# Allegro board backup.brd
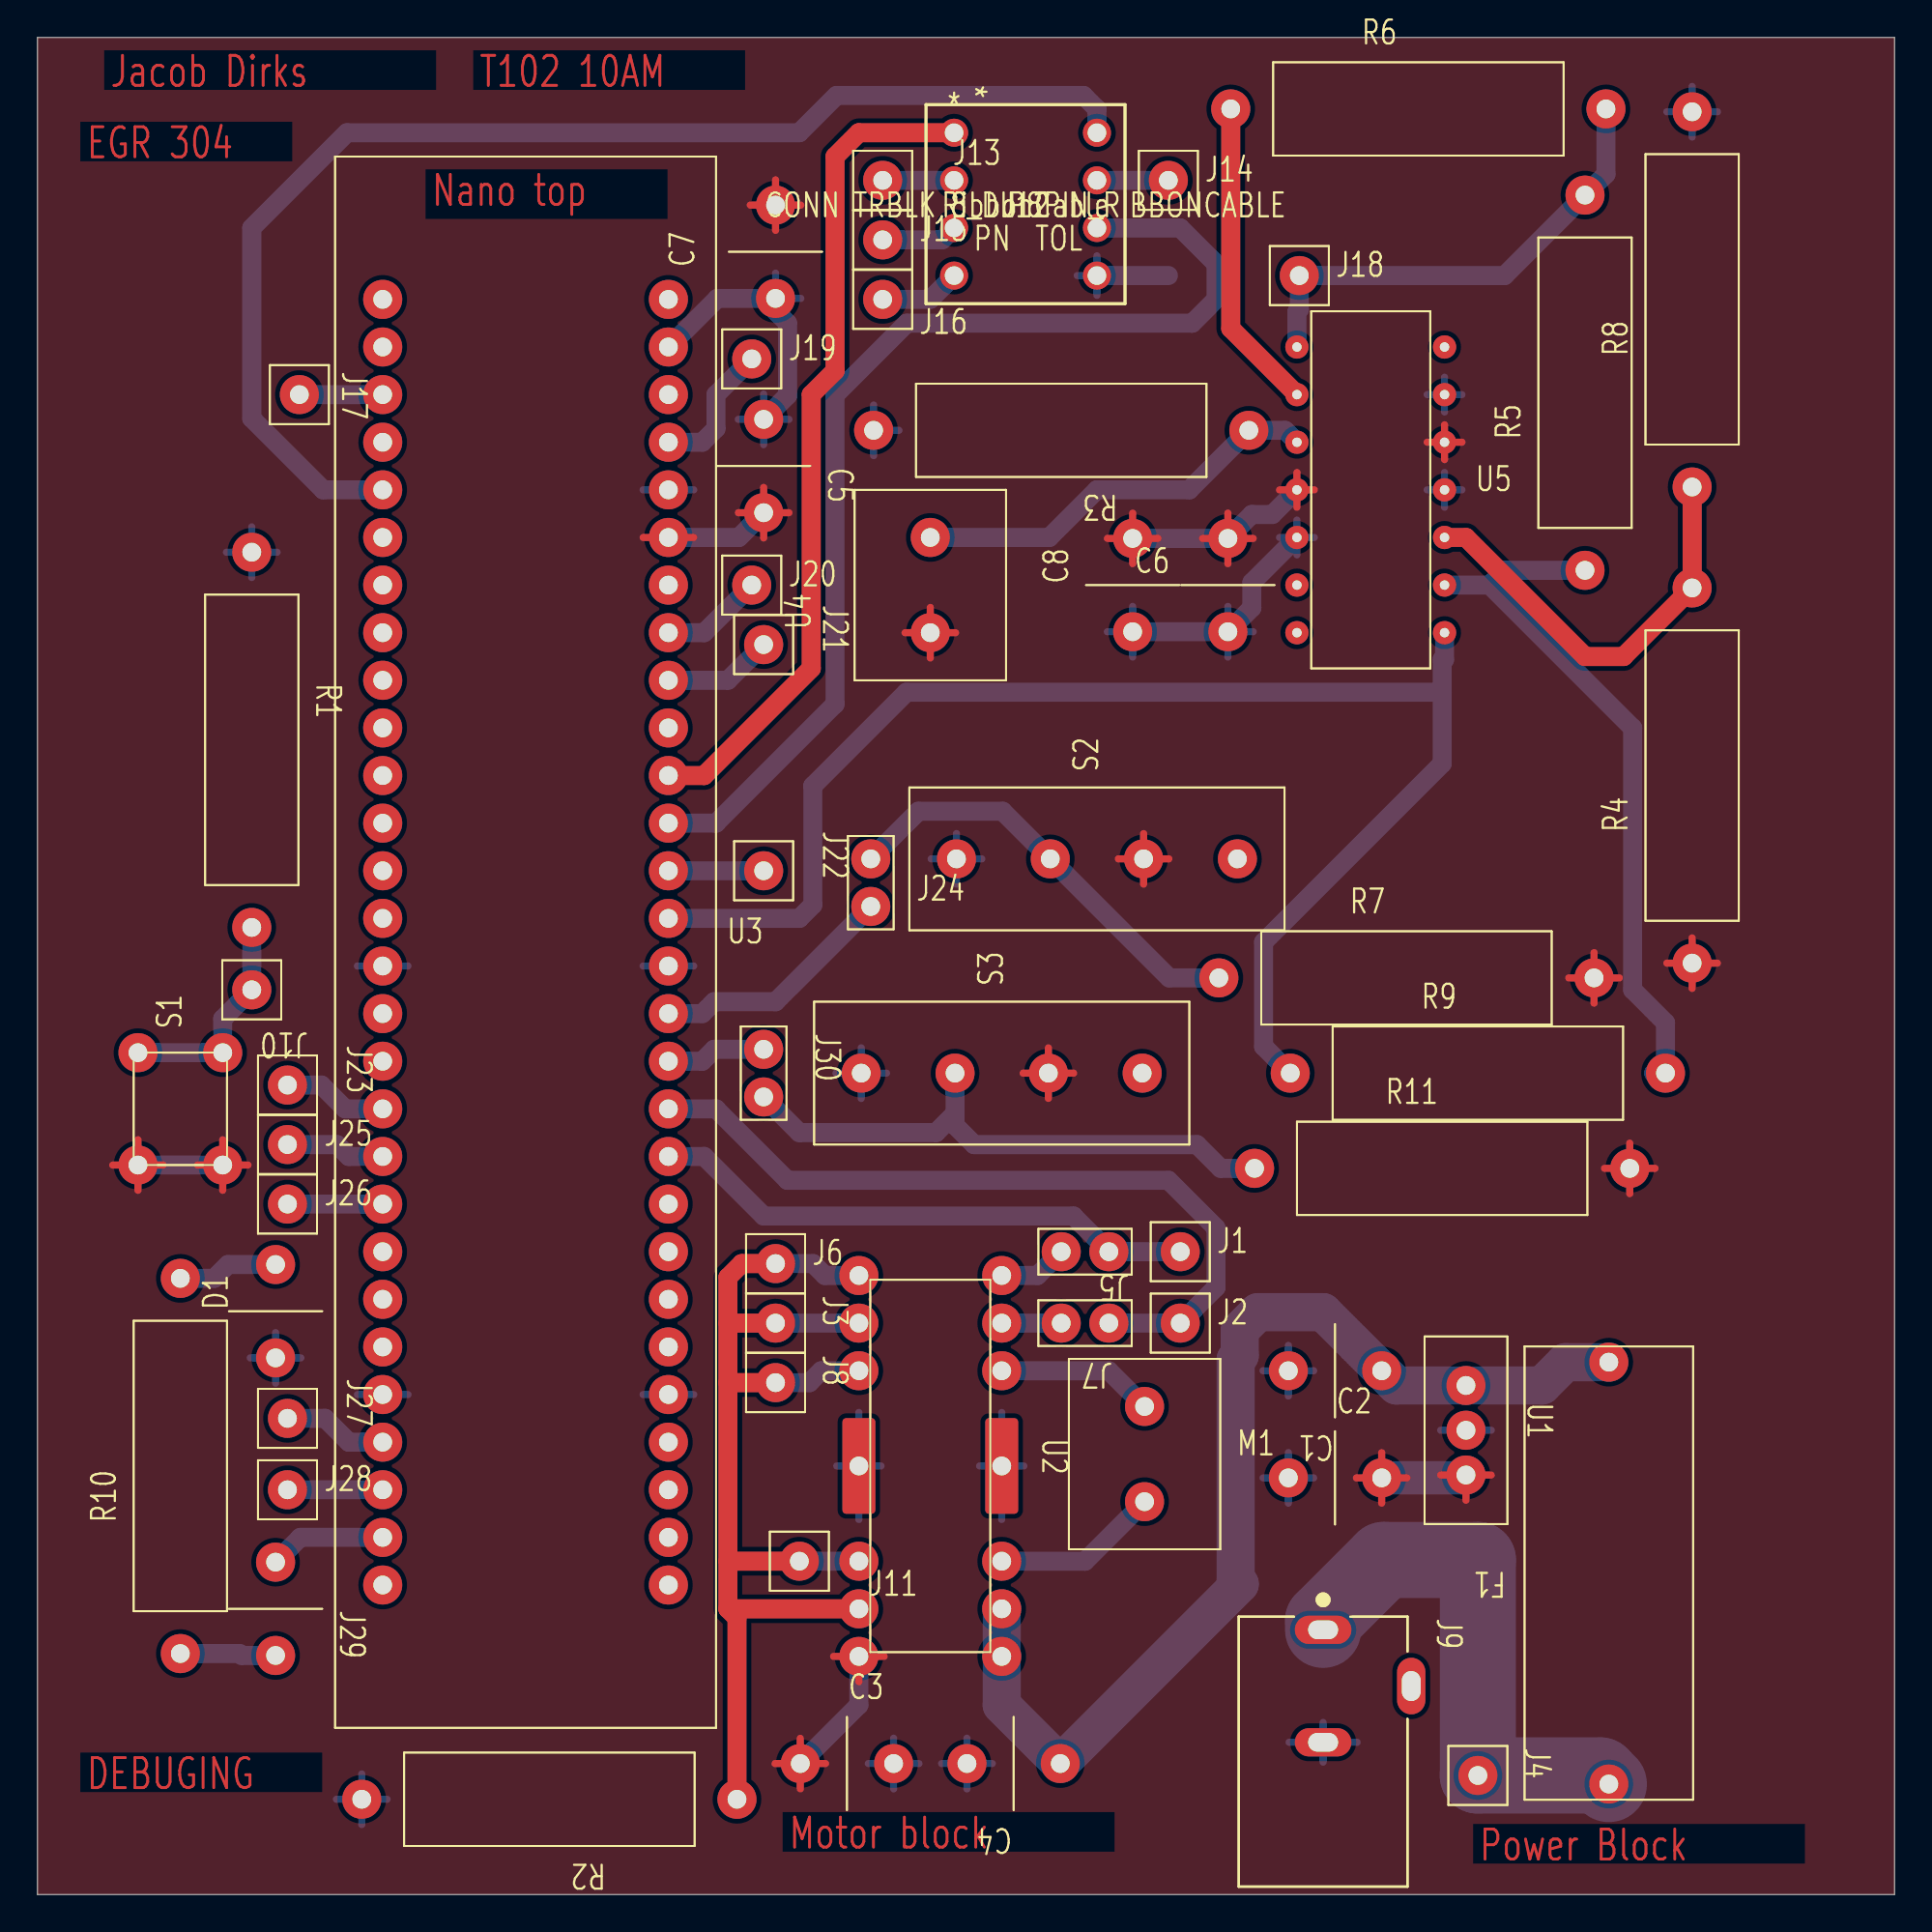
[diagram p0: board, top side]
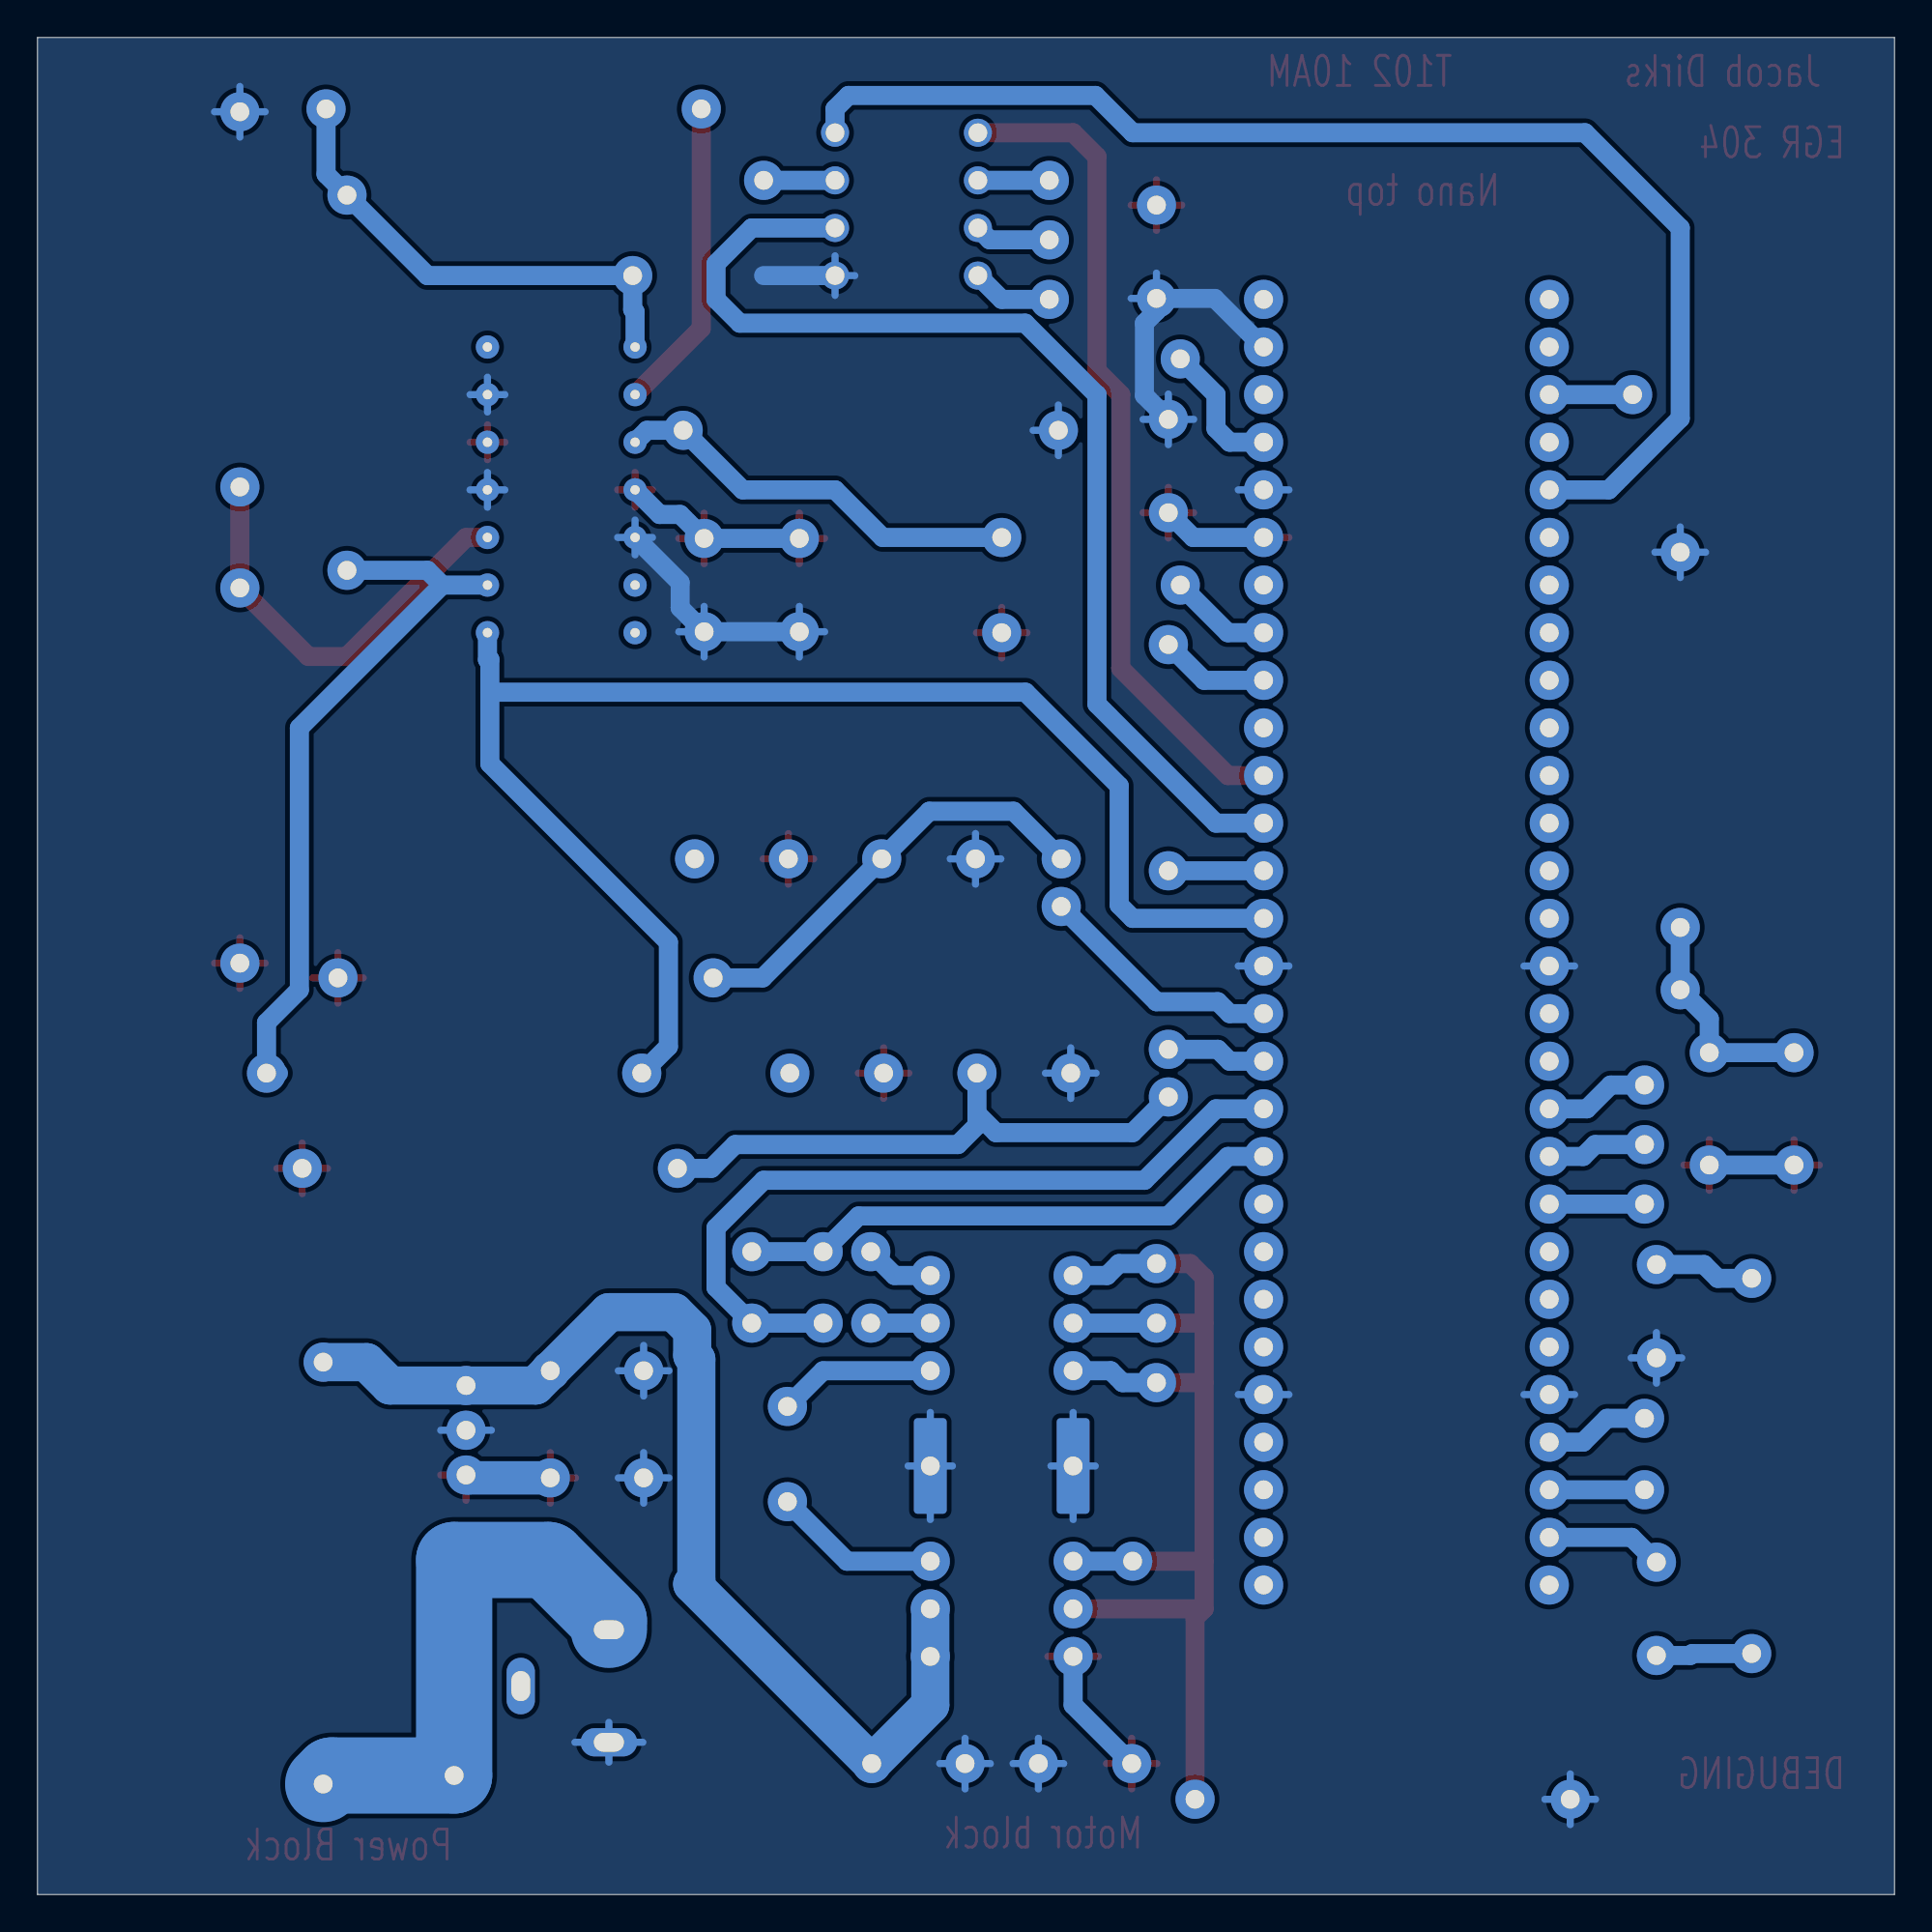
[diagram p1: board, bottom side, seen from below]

Outline 99.06 x 99.06 mm; copper layers: TOP, BOTTOM. Coordinates in mm from the lower left corner of the outline.
Outline path: 0,99.06 0,0 99.06,0 99.06,99.06 0,99.06

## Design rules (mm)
constraint set DEFAULT: min track width 0.381
net group N934900: nets N93718 N934900

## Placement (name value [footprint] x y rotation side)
C1  .33uf 50V  [CAPACITOR]  69.22 27.94 180 top
C2  .1uF 50V  [CAPACITOR]  69.22 22.22 0 top
C3  .1uF 50V  [CAPACITOR]  43.18 6.99 0 top
C4  .1uF 50V  [CAPACITOR]  52.07 6.99 180 top
C5  .1uF 50V  [CAPACITOR]  38.73 76.2 270 top
C6  .1uF 50V  [CAPACITOR]  63.5 69.85 90 top
C7  .1uF 50V  [CAPACITOR]  39.37 87.63 90 top
C8  .1uF 50V  [CAPACITOR]  58.42 69.85 90 top
D1  BlueLED  [CAPACITOR]  12.7 31.12 90 top
F1  FUSE 1A  [FUSEHOLDER]  83.82 17.15 180 top
J1  TP2  [MALEPINHOLE]  60.96 34.29 0 top
J2  TP3  [MALEPINHOLE]  60.96 30.48 0 top
J3  TP5  [MALEPINHOLE]  39.37 30.48 0 top
J4  TP12  [MALEPINHOLE]  76.83 6.35 0 top
J5  Jumper_JMD  [JUMPER]  55.88 34.29 270 top
J6  TP4  [MALEPINHOLE]  39.37 33.66 0 top
J7  Jumper_JMD  [JUMPER]  55.88 30.48 270 top
J8  TP6  [MALEPINHOLE]  39.37 27.31 0 top
J9  Barrel_Jack_Switch_JMD  [BARRELJACKDEVELOPERS_JMD]  68.58 7.62 270 top
J10  TP13  [MALEPINHOLE]  11.43 48.26 270 top
J11  TP7  [MALEPINHOLE]  40.64 17.78 0 top
J12  RibbonCable  [DIP8PIN]  48.89 93.98 0 top
J13  TP8  [MALEPINHOLE]  45.09 91.44 0 top
J14  TP9  [MALEPINHOLE]  60.33 91.44 0 top
J15  TP10  [MALEPINHOLE]  45.09 88.26 0 top
J16  TP11  [MALEPINHOLE]  45.09 85.09 0 top
J17  gpio_RF0  [MALEPINHOLE]  13.97 80.01 0 top
J18  TP1  [MALEPINHOLE]  67.31 86.36 0 top
J19  gpio_RB7  [MALEPINHOLE]  38.1 81.92 0 top
J20  gpio_RA6  [MALEPINHOLE]  38.1 69.85 0 top
J21  gpio_RB3  [MALEPINHOLE]  38.73 66.68 0 top
J22  gpio_RA1  [MALEPINHOLE]  38.73 54.61 0 top
J23  gpio_RE2  [MALEPINHOLE]  13.34 43.18 0 top
J24  Jumper_JMD  [JUMPER]  44.45 53.97 0 top
J25  gpio_RC7  [MALEPINHOLE]  13.34 40 0 top
J26  gpio_RD0  [MALEPINHOLE]  13.34 36.83 0 top
J27  gpio_RF0  [MALEPINHOLE]  13.34 25.4 0 top
J28  gpio_RF1  [MALEPINHOLE]  13.34 21.59 0 top
J29  Jumper_JMD  [CAPACITOR]  12.7 15.24 270 top
J30  Jumper_JMD  [JUMPER]  38.73 43.81 0 top
M1  Motor_DC_JMD  [SCREWTERMINAL]  59.06 23.5 0 top
R1  1k .25w  [RESISTOR_INTRO]  11.43 61.59 270 top
R2  1k .25w  [RESISTOR_INTRO]  27.31 5.08 180 top
R3  10k .25W  [RESISTOR_INTRO]  54.61 78.11 180 top
R4  10k .25W  [RESISTOR_INTRO]  88.27 59.69 90 top
R5  1k .25w  [RESISTOR_INTRO]  82.55 80.64 90 top
R6  1k .25w  [RESISTOR_INTRO]  73.66 95.25 0 top
R7  10k .25W  [RESISTOR_INTRO]  73.03 48.9 0 top
R8  10k .25W  [RESISTOR_INTRO]  88.27 85.09 90 top
R9  10k .25W  [RESISTOR_INTRO]  76.83 43.81 0 top
R10  220 .25W  [RESISTOR_INTRO]  7.62 22.86 90 top
R11  10k .25W  [RESISTOR_INTRO]  74.93 38.74 0 top
S1  SW_DPST_JMD  [SW_DPST]  7.62 41.91 90 top
S2  Switch_limit_JMD  [LIMITSWITCH]  56.52 55.25 90 top
S3  Switch_limit_JMD  [LIMITSWITCH]  51.44 43.81 90 top
U1  LM7805_JMD  [LINEARVOLTREG]  76.2 24.77 0 top
U2  FAN8011N_JMD  [HBRIDGEWITHFIN]  45.09 22.86 0 top
U3  PIC18F57Q43_JMD  [MICROCHIP_PIC18F57Q43]  26.03 50.8 0 top
U4  MS_JMD  [SCREWTERMINAL]  47.62 69.85 180 top
U5  MCP6004_JMD  [OPAMPJMD]  71.12 74.93 0 top

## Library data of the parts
C1-C8 = CAPACITOR NON-POL
D1 = LED
F1 = FUSE
J1-J4 J6 J10 J13-J17 J20-J23 J25-J28 = MalePinPlaceHolder_JMD
J5 J7 J24 J29 J30 = jumper_jmd
J8 = malePinPlaceHolderOutput_JMD_0
J9 = Barrel_Jack_Switch_JMD
J11 = malePinPlaceHolderOutput_JMD_1
J12 = CONN TRBLK 8: User Part Number: PN; Tolerance: TOL
J18 = MalePinPlaceHolder_JMD_6
J19 = malePinPlaceHolderOutput_JMD
M1 = Motor_DC_JMD
R1-R11 = RESISTOR
S1 = SW_DPST_JMD
S2 S3 = 463093691402_Limit_JMD
U1 = LM7805_JMD_0
U2 = FAN8011N_JMD_2
U3 = PIC18F57Q43_JMD
U4 = MoistureSenosr_JMD
U5 = MCP6004_JMD

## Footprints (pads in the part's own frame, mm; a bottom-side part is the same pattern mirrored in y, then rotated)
BARRELJACKDEVELOPERS_JMD
  oval 1.508x3.016 hole 1x1.6: 1(-6.5,0) 2(-0.5,0)
  oval 3.016x1.508 hole 1.6x1: 3(-3.5,4.7)
CAPACITOR
  round 2.083 hole 1.001: 1(-2.489,0) 2(2.489,0)
DIP8PIN
  round 1.499 hole 0.991: 1(0,0) 2(7.62,0) 3(0,-2.54) 4(7.62,-2.54) 5(0,-5.08) 6(7.62,-5.08) 7(0,-7.62) 8(7.62,-7.62)
FUSEHOLDER
  round 2.083 hole 1.001: 1(0,11.252) 2(0,-11.252)
HBRIDGEWITHFIN
  round 2.083 hole 1.001: 1(-1.27,10.16) 2(-1.27,7.62) 3(-1.27,5.08) 4(-1.27,-5.08) 5(-1.27,-7.62) 6(-1.27,-10.16) 7(6.35,-10.16) 8(6.35,-7.62) 9(6.35,-5.08) 10(6.35,5.08) 11(6.35,7.62) 12(6.35,10.16)
  rrect 1.753x5.1 hole 1.001: FIN(-1.27,0) FIN2(6.35,0)
JUMPER
  round 2.083 hole 1.001: 1(0,1.27) 2(0,-1.27)
LIMITSWITCH
  round 2.083 hole 1.001: 1(0,7.493) 2(0,2.489) 3(0,-2.489) 4(0,-7.493)
LINEARVOLTREG
  round 2.083 hole 1.001: 1(0,2.388) 2(0,0) 3(0,-2.388)
MALEPINHOLE
  round 2.083 hole 1.001: 1(0,0)
MICROCHIP_PIC18F57Q43
  round 2.083 hole 1.001: 1(7.62,34.29) 2(7.62,31.75) 3(7.62,29.21) 4(7.62,26.67) 5(7.62,24.13) 6(7.62,21.59) 7(7.62,19.05) 8(7.62,16.51) 9(7.62,13.97) 10(7.62,11.43) 11(7.62,8.89) 12(7.62,6.35) 13(7.62,3.81) 14(7.62,1.27) 15(7.62,-1.27) 16(7.62,-3.81) 17(7.62,-6.35) 18(7.62,-8.89) 19(7.62,-11.43) 20(7.62,-13.97) 21(7.62,-16.51) 22(7.62,-19.05) 23(7.62,-21.59) 24(7.62,-24.13) 25(7.62,-26.67) 26(7.62,-29.21) 27(7.62,-31.75) 28(7.62,-34.29) 29(-7.62,34.29) 30(-7.62,31.75) 31(-7.62,29.21) 32(-7.62,26.67) 33(-7.62,24.13) 34(-7.62,21.59) 35(-7.62,19.05) 36(-7.62,16.51) 37(-7.62,13.97) 38(-7.62,11.43) 39(-7.62,8.89) 40(-7.62,6.35) 41(-7.62,3.81) 42(-7.62,1.27) 43(-7.62,-1.27) 44(-7.62,-3.81) 45(-7.62,-6.35) 46(-7.62,-8.89) 47(-7.62,-11.43) 48(-7.62,-13.97) 49(-7.62,-16.51) 50(-7.62,-19.05) 51(-7.62,-21.59) 52(-7.62,-24.13) 53(-7.62,-26.67) 54(-7.62,-29.21) 55(-7.62,-31.75) 56(-7.62,-34.29)
OPAMPJMD
  round 1.245 hole 0.5: 1(-3.937,7.62) 2(-3.937,5.08) 3(-3.937,2.54) 4(-3.937,0) 5(-3.937,-2.54) 6(-3.937,-5.08) 7(-3.937,-7.62) 8(3.937,-7.62) 9(3.937,-5.08) 10(3.937,-2.54) 11(3.937,0) 12(3.937,2.54) 13(3.937,5.08) 14(3.937,7.62)
RESISTOR_INTRO
  round 2.083 hole 1.001: 1(-10.008,0) 2(10.008,0)
SCREWTERMINAL
  round 2.083 hole 1.001: 1(0,2.54) 2(0,-2.54)
SW_DPST
  round 2.083 hole 1.001: 1(-2.997,2.261) 2(2.997,2.261) 3(-2.997,-2.261) 4(2.997,-2.261)

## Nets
+5V: C2.2 C3.1 C5.2 C6.2 C7.2 C8.2 R4.1 R7.2 R11.2 S1.1(\PASSIVE\) S1.3 S2.3 S3.3 U1.3(\OUTPUT\) U2.6(\VCC\) U3.6(\VTG\) U4.1 U5.4 U5.12
+9V: C1.1 C4.1 F1.2 U1.1 U2.7 U2.8
GND: C1.2 C2.1 C3.2 C4.2 C5.1 C6.1 C7.1 C8.1 D1.1(\CATHODE\) J9.2(\SPRING\) J12.8 R1.1 R2.2 R3.2 R8.2 S2.1 S3.1 U1.2 U2.FIN U2.FIN2 U3.2 U3.5 U3.15 U3.24 U3.43 U3.52 U5.5 U5.11(\VSS\) U5.13
VBUS: U3.1
AMPSIG: R5.1 R9.2 U5.9
BACKLIMIT: J30.1 U3.17
INVAMP: R6.1 U5.2
MRETURN: J12.6 U3.12
MSOUT: R9.1 U3.14 U5.8
OUT1: J18.1(\PORT\) R5.2 R6.2 U5.1
PSIGNAL: J12.1 U3.11
RSIGNAL: J12.2 U3.33
SIGBACK: J1.1(\PORT\) J5.1 U3.19
SIGFORWARD: J2.1(\PORT\) J7.1 U3.18
VREF: R4.2 R8.1 U5.10
N91840: J3.1(\PORT\) J6.1(\PORT\) J8.1 J11.1 R2.1 U2.1 U2.2 U2.3 U2.4 U2.5
N91848: J7.2 U2.11
N91894: M1.1 U2.10
N91902: F1.1 J4.1(\PORT\) J9.1
N92202: M1.2(-) U2.9
N93412: J24.2 U3.16
N93642: J27.1(\PORT\) U3.53
N93710: J29.1 U3.55
N93718: J29.2 R10.1
N93780: J30.2 R11.1 S3.2
N113659: J10.1(\PORT\) R1.2 S1.2 S1.4
N116351: J24.1 R7.1 S2.2
N125765: R3.1 U4.2 U5.3
N129031: J12.4 J14.1(\PORT\)
N923142: J12.3 J13.1(\PORT\)
N923144: J12.5 J15.1(\PORT\)
N923146: J12.7 J16.1(\PORT\)
N926043: J19.1 U3.4
N926047: J20.1(\PORT\) U3.8
N926048: J21.1(\PORT\) U3.9
N934900: D1.2 R10.2
N9170211: J5.2 U2.12
N9260427: J17.1(\PORT\) U3.31
N9260442: J23.1(\PORT\) U3.46
N9260443: J25.1(\PORT\) U3.47
N9260444: J26.1(\PORT\) U3.48
N9260450: J28.1(\PORT\) U3.54
N9260454: J22.1(\PORT\) U3.13

Pads without a net: J9 3; S2 4; S3 4; U3 3 7 10 20 21 22 23 25 26 27 28 29 30 32 34 35 36 37 38 39 40 41 42 44 45 49 50 51 56; U5 6 7 14

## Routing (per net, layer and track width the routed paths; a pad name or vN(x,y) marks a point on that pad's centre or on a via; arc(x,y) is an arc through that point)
+5V: length 125.2
  TOP w0.381: U5.12 75.06,78.4 ; U5.12 75.06,76.54 ; U5.12 74.13,77.47 ; U5.12 75.98,77.47 ; C6.2 64.85,72.34 ; C6.2 62.15,72.34 ; C6.2 63.5,73.69 ; C6.2 63.5,70.99 ; 47.62,65.96 U4.1 ; U4.1 46.28,67.31 ; U4.1 47.62,68.66 ; U4.1 48.97,67.31 ; S3.3 53.92,45.16 ; S3.3 53.92,42.47 ; S3.3 52.58,43.81 ; S3.3 55.27,43.81 ; S1.1 6.71,38.91 ; S1.1 5.36,37.57 ; S1.1 4.01,38.91 ; S1.1 5.36,40.26 ; 58.42,70.99 C8.2 ; C8.2 58.42,73.69 ; C8.2 59.77,72.34 ; C8.2 57.07,72.34 ; R7.2 84.38,48.9 ; R7.2 83.03,47.55 ; R7.2 81.69,48.9 ; R7.2 83.03,50.24 ; 71.7,20.88 C2.2 ; C2.2 71.7,23.57 ; C2.2 70.36,22.22 ; C2.2 73.05,22.22 ; C3.1 42.04,6.99 ; C3.1 40.69,5.64 ; C3.1 39.34,6.99 ; C3.1 40.69,8.33 ; R4.1 88.27,51.03 ; R4.1 89.61,49.68 ; R4.1 88.27,48.34 ; R4.1 86.92,49.68 ; 43.81,11.35 U2.6 ; U2.6 45.16,12.7 ; U2.6 42.47,12.7 ; U5.4 68.11,74.93 ; U5.4 66.26,74.93 ; U5.4 67.18,75.86 ; U5.4 67.18,74 ; S2.3 59,56.59 ; S2.3 59,53.9 ; S2.3 60.35,55.25 ; S2.3 57.66,55.25 ; 74.85,22.38 U1.3 ; U1.3 77.55,22.38 ; U1.3 76.2,21.03 ; R11.2 84.94,40.08 ; R11.2 86.28,38.74 ; R11.2 83.59,38.74 ; R11.2 84.94,37.39 ; 38.02,90.12 C7.2 ; C7.2 39.37,88.77 ; C7.2 39.37,91.47 ; C7.2 40.72,90.12 ; C5.2 40.08,73.71 ; C5.2 37.39,73.71 ; C5.2 38.73,72.36 ; C5.2 38.73,75.06 ; 8.53,38.91 S1.3 ; S1.3 9.88,40.26 ; S1.3 9.88,37.57 ; S1.3 11.23,38.91 ; 35,72.39 U3.6 32.31,72.39
  BOTTOM w1.016: S1.1 S1.3 ; U3.6 37.41,72.39 C5.2 ; U2.6 43.81,10.11 C3.1 ; C8.2 C6.2 64.78,73.62 65.87,73.62 U5.4
  BOTTOM w1.778: C2.2 76.05,22.22 U1.3
+9V: length 59
  BOTTOM w2.032: F1.2 81.5,28.4 80.26,27.15 U1.1 72.49,27.15 C1.1 68.58,31.06 65.1,31.06 64.14,30.1 64.14,28.77 63.91,28.55 63.91,16.78 64.14,16.56 C4.1 51.44,10.11 U2.7 U2.8
GND: length 156.2
  BOTTOM w0.381: S3.1 45.29,43.81 ; S3.1 43.94,45.17 ; S3.1 43.94,42.46 ; S3.1 42.59,43.81 ; J9.2 70.39,8.12 ; J9.2 68.58,9.18 ; J9.2 66.77,8.12 ; J9.2 68.58,7.06 ; R2.2 17.3,6.43 ; R2.2 15.95,5.08 ; R2.2 17.3,3.73 ; R2.2 18.65,5.08 ; C4.2 49.58,8.34 ; C4.2 50.93,6.99 ; C4.2 48.23,6.99 ; C4.2 49.58,5.63 ; 40.72,85.14 C7.1 39.37,86.49 ; R3.2 45.95,78.11 ; R3.2 44.6,76.75 ; R3.2 44.6,79.46 ; 45.67,5.63 C3.2 ; C3.2 44.32,6.99 ; C3.2 45.67,8.34 ; C3.2 47.02,6.99 ; 74.85,24.77 U1.2 77.55,24.77 ; 43.81,20 U2.FIN ; U2.FIN 43.81,25.72 ; U2.FIN 45,22.86 ; U2.FIN 42.63,22.86 ; 65.38,27.94 C1.2 ; C1.2 66.73,26.59 ; C1.2 66.73,29.29 ; C1.2 68.08,27.94 ; U5.11 75.06,75.86 ; U5.11 75.98,74.93 ; U5.11 74.13,74.93 ; U5.11 75.06,74 ; U5.5 67.18,73.32 ; U5.5 68.11,72.39 ; U5.5 66.26,72.39 ; U5.5 67.18,71.46 ; R8.2 89.62,95.1 ; R8.2 86.91,95.1 ; R8.2 88.27,96.45 ; R8.2 88.27,93.75 ; 35.01,74.93 U3.5 32.3,74.93 ; 17.06,26.67 U3.52 19.77,26.67 ; 57.07,67.36 C8.1 ; C8.1 58.42,68.71 ; C8.1 58.42,66.01 ; U5.13 75.06,80.94 ; U5.13 75.06,79.08 ; U5.13 75.98,80.01 ; U5.13 74.13,80.01 ; 38.73,77.34 C5.1 ; C5.1 38.73,80.04 ; C5.1 37.38,78.69 ; C5.1 40.09,78.69 ; 32.3,49.53 U3.15 35.01,49.53 ; C2.1 66.73,23.58 ; C2.1 65.38,22.22 ; C2.1 66.73,20.87 ; C2.1 68.08,22.22 ; 10.08,71.6 R1.1 ; R1.1 11.43,70.25 ; R1.1 12.78,71.6 ; R1.1 11.43,72.95 ; D1.1 12.7,29.98 ; D1.1 14.05,28.63 ; D1.1 12.7,27.28 ; D1.1 11.35,28.63 ; C6.1 63.5,68.71 ; C6.1 64.85,67.36 ; C6.1 63.5,66.01 ; 35.01,26.67 U3.24 32.3,26.67 ; 49.02,53.89 S2.1 ; S2.1 49.02,56.6 ; S2.1 50.37,55.25 ; S2.1 47.67,55.25 ; U2.FIN2 52.62,22.86 ; U2.FIN2 50.25,22.86 ; U2.FIN2 51.44,20 ; U2.FIN2 51.44,25.72 ; 19.77,49.53 U3.43 17.06,49.53 ; 55.46,86.36 J12.8 ; J12.8 56.52,85.31 ; J12.8 56.52,87.41
  BOTTOM w1.016: 60.33,86.36 J12.8 ; U3.2 33.67,82.55 36.26,85.14 C7.1 39.37,84.46 40.01,83.82 40.01,79.97 C5.1 ; U5.5 64.78,69.99 64.78,68.64 C6.1 C8.1
AMPSIG: length 38.4
  BOTTOM w1.016: 86.21,43.81 R9.2 86.84,46.51 85.09,48.26 85.09,62.23 77.47,69.85 ; R5.1 78.26,70.64 77.47,69.85 ; 77.47,69.85 U5.9
BACKLIMIT: length 5.3
  BOTTOM w1.016: J30.1 36.1,45.09 35.46,44.45 U3.17
INVAMP: length 16.7
  TOP w1.016: U5.2 63.65,83.54 R6.1
MRETURN: length 59.5
  BOTTOM w1.016: U3.12 36.2,57.15 42.55,63.5 42.55,80.01 42.56,80.01 46.37,83.82 61.59,83.82 62.86,85.09 62.86,87 60.96,88.9 J12.6
MSOUT: length 78.1
  BOTTOM w1.016: 74.93,64.13 74.93,60.33 65.41,50.8 65.41,45.24 R9.1 ; 74.93,64.13 46.36,64.13 41.36,59.14 41.36,52.79 40.64,52.07 U3.14 ; 74.93,64.13 74.93,65.88 75.06,65.88 U5.8
OUT1: length 25.9
  BOTTOM w1.016: U5.1 67.18,84.43 67.31,84.55 J18.1 78.26,86.36 R5.2 83.67,91.77 R6.2
PSIGNAL: length 44.7
  TOP w1.016: J12.1 43.81,93.98 42.55,92.71 42.55,81.28 41.28,80.01 41.28,65.41 35.56,59.69 U3.11
RSIGNAL: length 68.3
  BOTTOM w1.016: U3.33 15.24,74.93 11.43,78.74 11.43,88.9 16.51,93.98 40.64,93.98 42.63,95.97 55.8,95.97 56.52,95.25 J12.2
SIGBACK: length 29.4
  BOTTOM w1.016: U3.19 35.56,39.37 38.73,36.19 55.26,36.19 57.15,34.31 57.15,34.29 J1.1
SIGFORWARD: length 41.5
  BOTTOM w1.016: U3.18 36.2,41.91 40,38.1 60.33,38.1 62.86,35.56 62.86,32.38 J2.1 57.15,30.48
VREF: length 22.7
  TOP w1.016: R8.1 R4.2 84.61,66.04 82.55,66.04 76.2,72.39 U5.10
N91840: length 63.8
  TOP w1.016: R2.1 37.31,14.76 36.83,15.24 ; 36.83,17.78 36.83,27.31 ; 36.83,17.78 J11.1 ; 36.83,17.78 36.83,15.24 ; 36.83,27.31 J8.1 ; 36.83,27.31 36.83,30.48 ; J6.1 37.57,33.66 36.83,32.92 36.83,30.48 ; U2.5 36.83,15.24 ; J3.1 36.83,30.48
  BOTTOM w1.016: J11.1 U2.4 ; J8.1 41.18,27.31 41.81,27.94 U2.3 ; U2.1 42.01,33.02 41.37,33.66 J6.1 ; U2.2 J3.1
N91848: length 3.2
  BOTTOM w1.016: J7.2 U2.11
N91894: length 8.4
  BOTTOM w1.016: M1.1 57.15,27.94 U2.10
N91902: length 28.8
  BOTTOM w4.064: F1.1 83.36,6.35 J4.1 76.83,17.85 71.82,17.85 68.58,14.61 J9.1
N92202: length 8.9
  BOTTOM w1.016: U2.9 55.88,17.78 M1.2
N93412: length 13.2
  BOTTOM w1.016: U3.16 35.46,46.99 36.1,47.62 39.37,47.62 J24.2
N93642: length 5.6
  BOTTOM w1.016: U3.53 16.61,24.13 15.34,25.4 J27.1
N93710: length 6.3
  BOTTOM w1.016: J29.1 14.02,19.05 U3.55
N93718: length 5.1
  BOTTOM w1.016: J29.2 10.89,12.75 10.79,12.85 R10.1
N93780: length 31.1
  BOTTOM w1.016: J30.2 40.64,40.64 47.93,40.64 48.95,41.66 ; 48.95,41.66 S3.2 ; 48.95,41.66 48.95,41.02 49.96,40 61.84,40 63.11,38.74 R11.1
N113659: length 11.8
  BOTTOM w1.016: S1.2 S1.4 9.88,46.71 J10.1 R1.2
N116351: length 23.3
  BOTTOM w1.016: R7.1 60.38,48.9 S2.2 51.49,57.78 46.99,57.78 J24.1
N125765: length 22.2
  BOTTOM w1.016: U4.2 53.98,72.39 56.52,74.93 61.44,74.93 R3.1 66.55,78.11 U5.3
N129031: length 3.8
  BOTTOM w1.016: J12.4 J14.1
N923142: length 3.8
  BOTTOM w1.016: J12.3 J13.1
N923144: length 4.1
  BOTTOM w1.016: J15.1 48.26,88.26 J12.5
N923146: length 4.3
  BOTTOM w1.016: J16.1 47.62,85.09 J12.7
N926043: length 7.3
  BOTTOM w1.016: U3.4 35.46,77.47 36.2,78.2 36.2,80.01 J19.1
N926047: length 5.5
  BOTTOM w1.016: U3.8 35.56,67.31 J20.1
N926048: length 5.9
  BOTTOM w1.016: J21.1 36.83,64.77 U3.9
N934900: length 5.4
  BOTTOM w1.016: D1.2 10.16,33.6 9.43,32.87 R10.2
N9170211: length 3.7
  BOTTOM w1.016: U2.12 53.34,33.02 J5.2
N9260427: length 4.4
  BOTTOM w1.016: J17.1 U3.31
N9260442: length 5.6
  BOTTOM w1.016: J23.1 15.14,43.18 16.41,41.91 U3.46
N9260443: length 5.3
  BOTTOM w1.016: U3.47 16.61,39.37 15.97,40 J25.1
N9260444: length 5.1
  BOTTOM w1.016: U3.48 J26.1
N9260450: length 5.1
  BOTTOM w1.016: U3.54 J28.1
N9260454: length 5.1
  BOTTOM w1.016: U3.13 J22.1

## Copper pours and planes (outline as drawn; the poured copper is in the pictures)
+5V on TOP: 0,99.06 0,0 99.06,0 99.06,99.06
GND on BOTTOM: 99.06,0 99.06,99.06 0,99.06 0,0

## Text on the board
TOP: EGR 304 | DEBUGING | Jacob Dirks | Nano top | T102 10AM | Motor block | Power Block
COMPVAL_TYPE_TOP: Dirks | 102
